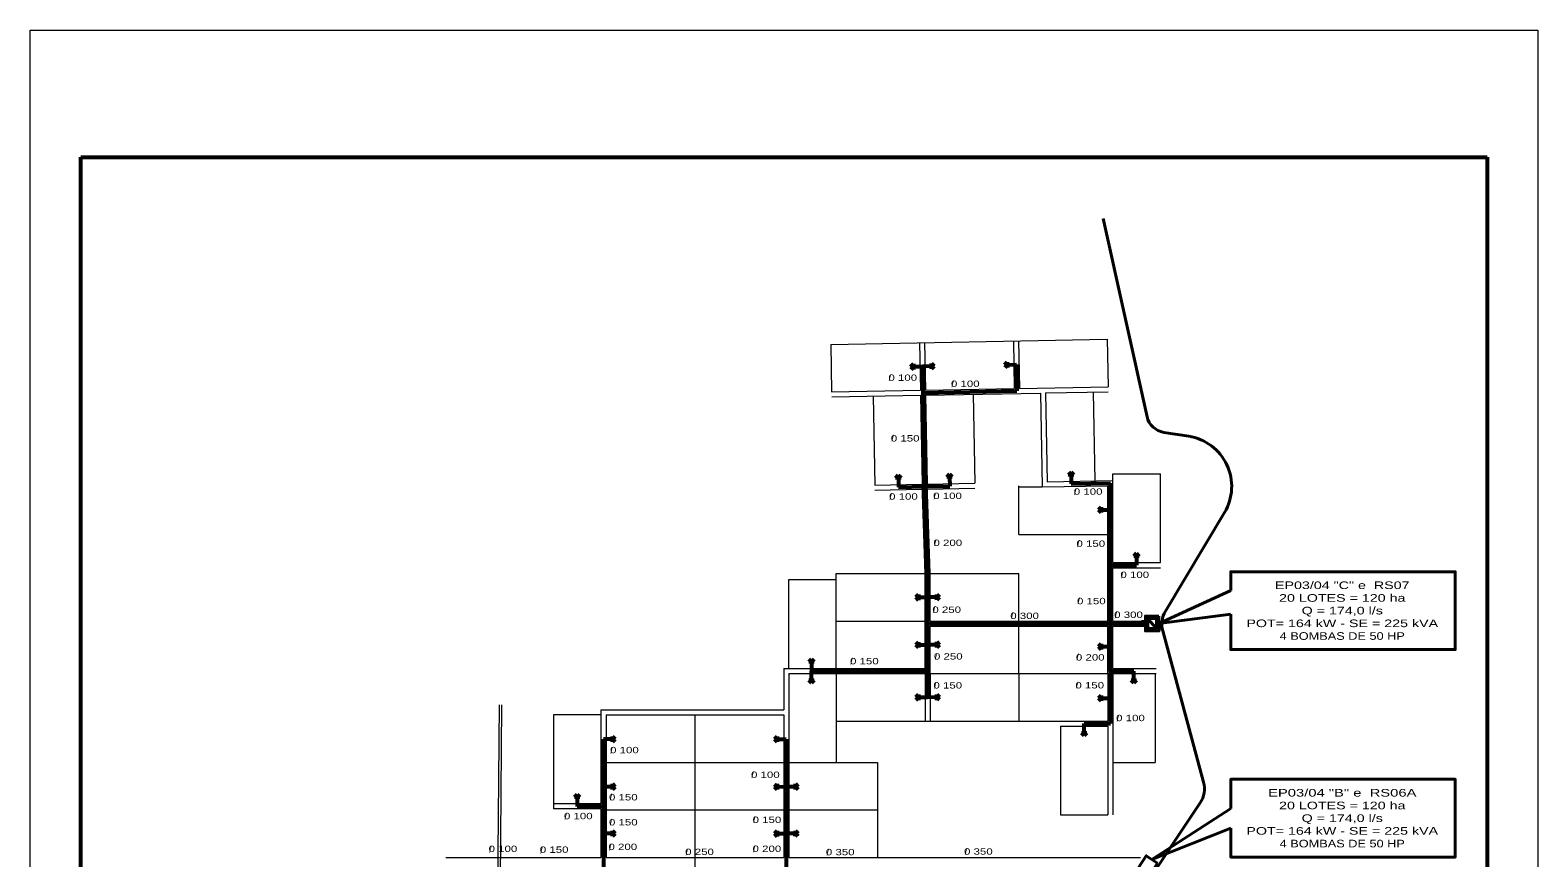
# Model space of a CAD drawing. Extents: x 312964 to 351929, y 9004151 to 9034973.
# Drawn here: x 342096 to 348036, y 9031712 to 9034973 of the extents above; entities that cross this region are included whole.
import ezdxf
from ezdxf.enums import TextEntityAlignment as Align

# ---------------------------------------------------------------- set-up
doc = ezdxf.new("R2010")
doc.units = 0
doc.header["$LTSCALE"] = 10
for name, color, linetype, lineweight in [('1', 7, 'Continuous', 13), ('2', 7, 'Continuous', 53), ('6', 7, 'Continuous', 13)]:
    doc.layers.add(name, color=color, linetype=linetype, lineweight=lineweight)

msp = doc.modelspace()

# ---------------------------------------------------------------- linework, layer by layer
at = {"layer": '1'}
for p, q in [((342096.46, 9030772.79), (342096.46, 9034972.79)), ((345250.43, 9033734.99), (345253.92, 9033548.02)), ((345600.37, 9033741.53), (345603.86, 9033554.56)), ((345620.36, 9033741.9), (345623.86, 9033554.94)), ((345970.3, 9033748.45), (345973.8, 9033561.48)), ((345990.3, 9033748.82), (345993.79, 9033561.85)), ((345253.92, 9033548.02), (345603.86, 9033554.56)), ((345623.86, 9033554.94), (345973.8, 9033561.48)), ((345993.79, 9033561.85), (346343.73, 9033568.39)), ((345254.3, 9033528.03), (345604.24, 9033534.57)), ((345417.27, 9033531.07), (345423.81, 9033181.13)), ((345604.24, 9033534.57), (345610.78, 9033184.49)), ((345624.23, 9033534.94), (346077.15, 9033543.41)), ((345624.23, 9033534.94), (345630.77, 9033185)), ((345811.2, 9033538.44), (345817.74, 9033188.5)), ((346097.15, 9033543.78), (346344.11, 9033548.4)), ((346097.15, 9033543.78), (346103.69, 9033193.84)), ((346284.12, 9033547.28), (346290.66, 9033197.34)), ((346103.69, 9033193.84), (346362.24, 9033198.67)), ((346362.24, 9033225.36), (346549.24, 9033225.36)), ((346362.24, 9032875.36), (346362.24, 9033225.36)), ((346549.24, 9032875.36), (346549.24, 9033225.36)), ((345423.81, 9033181.13), (345610.78, 9033184.63)), ((345424.18, 9033161.14), (345611.15, 9033164.63)), ((345622.24, 9032832.03), (345610.78, 9033184.49)), ((345630.77, 9033185), (345817.74, 9033188.5)), ((345642.24, 9032832.36), (345630.77, 9033185)), ((345631.15, 9033165.01), (345818.12, 9033168.5)), ((345992.24, 9032986.47), (345992.24, 9033178.3)), ((345992.24, 9033173.47), (346084.07, 9033173.47)), ((346342.24, 9032645.36), (346342.24, 9033178.3)), ((345992.24, 9032986.47), (346342.24, 9032986.47)), ((346362.24, 9032875.36), (346549.24, 9032875.36)), ((346362.24, 9032855.36), (346549.24, 9032855.36)), ((346362.24, 9032645.36), (346362.24, 9032855.36)), ((345085.24, 9032458.36), (345085.24, 9032808.36)), ((345085.24, 9032808.36), (345272.24, 9032808.36)), ((345272.24, 9032458.36), (345272.24, 9032832.36)), ((345272.24, 9032832.36), (345622.24, 9032832.36)), ((345622.24, 9032458.36), (345622.24, 9032832.03)), ((345642.24, 9032832.36), (345992.24, 9032832.36)), ((345642.24, 9032645.36), (345642.24, 9032832.36)), ((345992.24, 9032645.36), (345992.24, 9032832.36)), ((345272.24, 9032645.36), (345622.24, 9032645.36)), ((345642.24, 9032645.36), (346342.24, 9032645.36)), ((345642.24, 9032625.36), (346342.24, 9032625.36)), ((345642.24, 9032438.36), (345642.24, 9032625.36)), ((345992.24, 9032438.36), (345992.24, 9032625.36)), ((346342.24, 9032438.36), (346342.24, 9032625.36)), ((346362.24, 9032645.36), (346475.44, 9032645.36)), ((346362.24, 9032625.36), (346475.49, 9032625.36)), ((346362.24, 9032458.36), (346362.24, 9032625.36)), ((345065.24, 9032458.36), (345065.24, 9032295.36)), ((345065.24, 9032458.36), (345622.24, 9032458.36)), ((345085.24, 9032438.36), (345622.24, 9032438.36)), ((345085.24, 9032438.36), (345085.24, 9031714.36)), ((345272.24, 9032438.36), (345272.24, 9032088.36)), ((345622.24, 9032438.36), (345622.24, 9032251.36)), ((345642.24, 9032438.36), (345642.24, 9032251.36)), ((345642.24, 9032438.36), (346342.24, 9032438.36)), ((345992.24, 9032438.36), (345992.24, 9032251.36)), ((346342.24, 9032438.36), (346342.24, 9032251.36)), ((346362.24, 9032458.36), (346532.23, 9032458.36)), ((346362.24, 9032438.36), (346362.24, 9031881.36)), ((346362.24, 9032438.36), (346532.28, 9032438.36)), ((346529.24, 9032438.36), (346529.24, 9032088.36)), ((344158.24, 9032275.36), (344158.24, 9031905.36)), ((344345.24, 9032275.36), (344158.24, 9032275.36)), ((344345.24, 9032295.36), (345065.24, 9032295.36)), ((344345.24, 9032295.36), (344345.24, 9031925.36)), ((344365.24, 9032275.36), (345065.24, 9032275.36)), ((344365.24, 9032275.36), (344365.24, 9031714.36)), ((344715.24, 9032275.36), (344715.24, 9030385.36)), ((345065.24, 9032275.36), (345065.24, 9031714.36)), ((345272.24, 9032251.36), (346342.24, 9032251.36)), ((346155.24, 9032231.36), (346342.24, 9032231.36)), ((346155.24, 9032231.36), (346155.24, 9031881.36)), ((346342.24, 9032231.36), (346342.24, 9031881.36)), ((344365.24, 9032088.36), (345435.24, 9032088.36)), ((345085.24, 9032088.36), (345435.24, 9032088.36)), ((345435.24, 9032088.36), (345435.24, 9031714.36)), ((346362.24, 9032088.36), (346529.24, 9032088.36)), ((344345.24, 9031925.36), (344158.24, 9031925.36)), ((344345.24, 9031905.36), (344158.24, 9031905.36)), ((344345.24, 9031905.36), (344345.24, 9031714.36)), ((344365.24, 9031901.36), (345065.24, 9031901.36)), ((345085.24, 9031901.36), (345435.24, 9031901.36)), ((346155.24, 9031881.36), (346342.24, 9031881.36)), ((343734.24, 9031714.36), (344345.24, 9031714.36)), ((344365.24, 9031714.36), (345065.24, 9031714.36))]:
    msp.add_line(p, q, dxfattribs=at)
at = {"layer": '1', "lineweight": 53}
for p, q in [((342296.46, 9026772.79), (342296.46, 9034472.79)), ((342296.46, 9034472.79), (347836.46, 9034472.79)), ((347836.46, 9034472.79), (347836.46, 9026772.79))]:
    msp.add_line(p, q, dxfattribs=at)
at = {"layer": '1', "lineweight": 40}
for p, q in [((346496.92, 9033450.17), (346323.74, 9034231.36)), ((346661.08, 9033373.09), (346562.69, 9033388.44)), ((346569.07, 9032683.84), (346801.86, 9033072.77)), ((346490.49, 9032627.9), (346475.45, 9032642.86)), ((346490.45, 9032642.9), (346475.49, 9032627.86)), ((346500.42, 9032654.58), (346533.9, 9032616.34)), ((346719.85, 9032010.25), (346558.36, 9032606.33)), ((346471.21, 9031576.37), (346706.48, 9031928.55))]:
    msp.add_line(p, q, dxfattribs=at)
at = {"layer": '1'}
for points in [[(342096.46, 9034972.79), (348036.46, 9034972.79), (348036.46, 9030772.79)], [(345250.43, 9033734.99), (346340.24, 9033755.36), (346343.73, 9033568.39)], [(346077.15, 9033543.41), (346084.07, 9033173.47), (346342.24, 9033178.3)], [(345085.24, 9031714.36), (345435.24, 9031714.36), (346471.5, 9031714.36)]]:
    msp.add_lwpolyline(points, dxfattribs=at)
at = {"layer": '1', "lineweight": 40}
for points in [[(346543.78, 9032664.69), (346543.93, 9032606.37), (346490.54, 9032606.24), (346490.4, 9032664.56)], [(346475.45, 9032642.86), (346475.49, 9032627.86), (346490.49, 9032627.9), (346490.45, 9032642.9)], [(346533.81, 9032654.67), (346533.9, 9032616.34), (346500.52, 9032616.26), (346500.42, 9032654.58)], [(346500.42, 9032654.58), (346533.81, 9032654.67), (346533.9, 9032616.34)], [(346538.12, 9031691.25), (346506.14, 9031642.47), (346461.49, 9031671.75), (346493.47, 9031720.52)]]:
    msp.add_lwpolyline(points, close=True, dxfattribs=at)
for centre, radius, start, end in [((346575.02, 9033467.49), 80, 192.49974, 261.1331), ((346630.25, 9033175.48), 200, 329.09823, 81.13306), ((346654.88, 9032632.48), 100, 149.09824, 195.159), ((346623.33, 9031984.1), 100, 326.25468, 15.15895)]:
    msp.add_arc(centre, radius, start, end, dxfattribs=at)
at = {"layer": '2'}
for p, q in [((345565.5, 9033647.11), (345576.08, 9033658.09)), ((345565.5, 9033647.11), (345576.48, 9033636.53)), ((345576.08, 9033658.09), (345576.48, 9033636.53)), ((345576.27, 9033647.57), (345612.11, 9033648.23)), ((345647.96, 9033648.9), (345612.11, 9033648.23)), ((345612.11, 9033648.23), (345614.05, 9033544.75)), ((345648.15, 9033638.38), (345647.75, 9033659.94)), ((345658.73, 9033649.36), (345647.75, 9033659.94)), ((345658.73, 9033649.36), (345648.15, 9033638.38)), ((345935.43, 9033654.02), (345946.01, 9033665)), ((345935.43, 9033654.02), (345946.41, 9033643.45)), ((345946.01, 9033665), (345946.41, 9033643.45)), ((345946.21, 9033654.48), (345982.05, 9033655.15)), ((345982.05, 9033655.15), (345983.98, 9033551.67)), ((345614.05, 9033544.75), (345983.98, 9033551.67)), ((345614.05, 9033544.75), (345620.78, 9033184.82)), ((345516.49, 9033219.5), (345505.91, 9033208.52)), ((345527.47, 9033208.92), (345505.91, 9033208.52)), ((345516.49, 9033219.5), (345527.47, 9033208.92)), ((345516.95, 9033208.73), (345517.62, 9033172.89)), ((345718.52, 9033223.28), (345707.95, 9033212.3)), ((345729.5, 9033212.7), (345707.95, 9033212.3)), ((345718.52, 9033223.28), (345729.5, 9033212.7)), ((345718.98, 9033212.5), (345719.65, 9033176.66)), ((346197.26, 9033232.22), (346186.44, 9033221.48)), ((346208, 9033221.4), (346186.44, 9033221.48)), ((346197.26, 9033232.22), (346208, 9033221.4)), ((346197.48, 9033221.44), (346197.36, 9033185.59)), ((345517.62, 9033172.89), (345621.1, 9033174.82)), ((345616.17, 9033174.73), (345719.65, 9033176.66)), ((345632.24, 9032832.04), (345620.78, 9033184.68)), ((346197.36, 9033185.59), (346352.24, 9033188.49)), ((346352.24, 9032448.36), (346352.24, 9033188.49)), ((346305.61, 9033083.57), (346316.43, 9033094.32)), ((346305.61, 9033083.57), (346316.35, 9033072.76)), ((346316.43, 9033094.32), (346316.35, 9033072.76)), ((346316.39, 9033083.79), (346352.24, 9033083.67)), ((346455.64, 9032911.99), (346444.82, 9032901.25)), ((346466.38, 9032901.17), (346444.82, 9032901.25)), ((346455.64, 9032911.99), (346466.38, 9032901.17)), ((346455.86, 9032901.21), (346455.74, 9032865.36)), ((346352.24, 9032865.36), (346455.74, 9032865.36)), ((345585.61, 9032738.76), (345596.43, 9032749.5)), ((345585.61, 9032738.76), (345596.35, 9032727.94)), ((345596.43, 9032749.5), (345596.35, 9032727.94)), ((345596.39, 9032738.98), (345632.24, 9032738.86)), ((345668.09, 9032738.74), (345632.24, 9032738.86)), ((345668.05, 9032728.22), (345668.12, 9032749.78)), ((345678.87, 9032738.96), (345668.05, 9032728.22)), ((345678.87, 9032738.96), (345668.12, 9032749.78)), ((345632.24, 9032635.36), (346475.47, 9032635.36)), ((345585.61, 9032551.76), (345596.43, 9032562.5)), ((345585.61, 9032551.76), (345596.35, 9032540.94)), ((345596.43, 9032562.5), (345596.35, 9032540.94)), ((345596.39, 9032551.98), (345632.24, 9032551.86)), ((345668.09, 9032551.74), (345632.24, 9032551.86)), ((345668.05, 9032541.22), (345668.12, 9032562.78)), ((345678.87, 9032551.96), (345668.05, 9032541.22)), ((345678.87, 9032551.96), (345668.12, 9032562.78)), ((346305.61, 9032544.34), (346316.43, 9032555.08)), ((346305.61, 9032544.34), (346316.35, 9032533.52)), ((346316.43, 9032555.08), (346316.35, 9032533.52)), ((346316.39, 9032544.56), (346352.24, 9032544.44)), ((345174.72, 9032494.99), (345163.9, 9032484.25)), ((345185.46, 9032484.17), (345163.9, 9032484.25)), ((345174.72, 9032494.99), (345185.46, 9032484.17)), ((345174.94, 9032484.21), (345174.82, 9032448.36)), ((345174.7, 9032412.51), (345174.82, 9032448.36)), ((345632.24, 9032448.36), (345632.24, 9032344.86)), ((346352.24, 9032448.36), (346352.24, 9032241.36)), ((346352.24, 9032448.36), (346444.41, 9032448.36)), ((346444.29, 9032412.51), (346444.41, 9032448.36)), ((345164.18, 9032412.55), (345185.74, 9032412.47)), ((345174.92, 9032401.73), (345164.18, 9032412.55)), ((345174.92, 9032401.73), (345185.74, 9032412.47)), ((346433.77, 9032412.55), (346455.33, 9032412.47)), ((346444.51, 9032401.73), (346433.77, 9032412.55)), ((346444.51, 9032401.73), (346455.33, 9032412.47)), ((345585.61, 9032344.76), (345596.43, 9032355.5)), ((345585.61, 9032344.76), (345596.35, 9032333.94)), ((345596.43, 9032355.5), (345596.35, 9032333.94)), ((345596.39, 9032344.98), (345632.24, 9032344.86)), ((345668.09, 9032344.74), (345632.24, 9032344.86)), ((345668.05, 9032334.22), (345668.12, 9032355.78)), ((345678.87, 9032344.96), (345668.05, 9032334.22)), ((345678.87, 9032344.96), (345668.12, 9032355.78)), ((346305.61, 9032341.21), (346316.43, 9032351.95)), ((346305.61, 9032341.21), (346316.35, 9032330.39)), ((346316.43, 9032351.95), (346316.35, 9032330.39)), ((346316.39, 9032341.43), (346352.24, 9032341.31)), ((344391.05, 9032169.56), (344391.12, 9032191.12)), ((344401.87, 9032180.3), (344391.12, 9032191.12)), ((345028.61, 9032179.73), (345039.43, 9032190.47)), ((345039.43, 9032190.47), (345039.35, 9032168.91)), ((346238.1, 9032205.55), (346259.66, 9032205.47)), ((346248.84, 9032194.73), (346238.1, 9032205.55)), ((346248.62, 9032205.51), (346248.74, 9032241.36)), ((346248.74, 9032241.36), (346352.24, 9032241.36)), ((346248.84, 9032194.73), (346259.66, 9032205.47)), ((344391.09, 9032180.08), (344355.24, 9032180.2)), ((344401.87, 9032180.3), (344391.05, 9032169.56)), ((345028.61, 9032179.73), (345039.35, 9032168.91)), ((345039.39, 9032179.95), (345075.24, 9032179.83)), ((344251.64, 9031961.99), (344240.82, 9031951.25)), ((344262.38, 9031951.17), (344240.82, 9031951.25)), ((344251.64, 9031961.99), (344262.38, 9031951.17)), ((344251.86, 9031951.21), (344251.74, 9031915.36)), ((344391.09, 9031992.48), (344355.24, 9031992.6)), ((344391.05, 9031981.96), (344391.12, 9032003.52)), ((344401.87, 9031992.7), (344391.05, 9031981.96)), ((344401.87, 9031992.7), (344391.12, 9032003.52)), ((345029.17, 9031992.64), (345039.98, 9032003.38)), ((345029.17, 9031992.64), (345039.91, 9031981.83)), ((345039.98, 9032003.38), (345039.91, 9031981.83)), ((345039.95, 9031992.86), (345075.79, 9031992.74)), ((345111.64, 9031992.62), (345075.79, 9031992.74)), ((345111.61, 9031982.1), (345111.68, 9032003.66)), ((345122.42, 9031992.84), (345111.61, 9031982.1)), ((345122.42, 9031992.84), (345111.68, 9032003.66)), ((344355.24, 9031915.36), (344251.74, 9031915.36)), ((344391.09, 9031807.74), (344355.24, 9031807.86)), ((344391.05, 9031797.22), (344391.12, 9031818.78)), ((344401.87, 9031807.96), (344391.05, 9031797.22)), ((344401.87, 9031807.96), (344391.12, 9031818.78)), ((345028.61, 9031807.76), (345039.43, 9031818.5)), ((345028.61, 9031807.76), (345039.35, 9031796.94)), ((345039.43, 9031818.5), (345039.35, 9031796.94)), ((345039.39, 9031807.98), (345075.24, 9031807.86)), ((345111.09, 9031807.74), (345075.24, 9031807.86)), ((345111.05, 9031797.22), (345111.12, 9031818.78)), ((345121.87, 9031807.96), (345111.05, 9031797.22)), ((345121.87, 9031807.96), (345111.12, 9031818.78))]:
    msp.add_line(p, q, dxfattribs=at)
at = {"layer": '2', "lineweight": 40}
for p in [(346826.7, 9031907.46), (346826.7, 9031829.31)]:
    msp.add_line(p, (346515.8, 9031705.88), dxfattribs=at)
for points in [[(347004.19, 9032839.61), (347710.93, 9032839.61), (347710.93, 9032532.78), (346826.7, 9032532.78), (346826.7, 9032672.27)], [(346826.7, 9032765.47), (346826.7, 9032839.61), (347004.19, 9032839.61)], [(346826.7, 9032765.47), (346543.86, 9032635.53), (346826.7, 9032672.27)], [(347004.19, 9032022.03), (347710.93, 9032022.03), (347710.93, 9031715.2), (346826.7, 9031715.2), (346826.7, 9031829.31)], [(346826.7, 9031907.46), (346826.7, 9032022.03), (347004.19, 9032022.03)]]:
    msp.add_lwpolyline(points, dxfattribs=at)
at = {"layer": '2'}
for points in [[(345174.82, 9032448.36), (345632.24, 9032448.36), (345632.24, 9032832.36)], [(344355.24, 9032180.2), (344355.24, 9031704.36), (344355.24, 9031432.6)], [(345075.24, 9032179.83), (345075.24, 9031704.36), (345075.24, 9031433.86)]]:
    msp.add_lwpolyline(points, dxfattribs=at)
at = {"layer": '6'}
msp.add_line((343935.24, 9031098.44), (343945.24, 9032315.44), dxfattribs=at)
msp.add_lwpolyline([(343925.24, 9028600.36), (343934.24, 9029095.36), (343930.24, 9029625.36), (343925.24, 9030387.36), (343945.24, 9031098.36), (343955.24, 9032315.36)], dxfattribs=at)

# ---------------------------------------------------------------- texts
at = {"layer": '2'}
for p in [(345483.57, 9033590.74), (345731.05, 9033566.83), (345494.67, 9033352.9), (345486.74, 9033122.81), (345660.67, 9033125.05), (346214.41, 9033142.08), (345662.25, 9032940.69), (346226.04, 9032937.52), (346398.71, 9032814.05), (346228.15, 9032712.45), (345658.37, 9032677.71), (345965.85, 9032655.13), (346374.18, 9032656.52), (345332.95, 9032474.34), (345665.52, 9032493.36), (346223.47, 9032491.29), (345662.35, 9032379.24), (346221.36, 9032380.34), (346381.84, 9032249.32), (344387.09, 9032122.95), (344942.84, 9032026.89), (344385.02, 9031939.61), (344206.59, 9031863.54), (344385.02, 9031840.29), (344949.48, 9031850.84), (343909.66, 9031733.03), (344111.33, 9031729.66), (344381.77, 9031740.89), (344683.63, 9031722.91), (344948.92, 9031735.16), (345239.08, 9031721.78), (345783.88, 9031725.16)]:
    msp.add_text('/', height=25, dxfattribs=at).set_placement(p, align=Align.CENTER)
for s, height, width, p in [('0 100', 25, 1.35, (345534.26, 9033591.41)), ('0 100', 25, 1.35, (345780.76, 9033567.5)), ('0 150', 25, 1.35, (345543.85, 9033352.44)), ('0 100', 25, 1.35, (345536.91, 9033123.47)), ('0 100', 25, 1.35, (345710.84, 9033125.72)), ('0 100', 25, 1.35, (346264.65, 9033142.65)), ('0 200', 25, 1.35, (345711.75, 9032940.92)), ('0 150', 25, 1.35, (346275.21, 9032937.66)), ('0 100', 25, 1.35, (346448.35, 9032815.09)), ('EP03/04 "C" e  RS07', 30, 1.4, (347265.88, 9032771.27)), ('0 150', 25, 1.35, (346277.32, 9032711.54)), ('20 LOTES = 120 ha', 30, 1.4, (347265.88, 9032721.27)), ('0 250', 25, 1.35, (345707.47, 9032677.45)), ('0 300', 25, 1.35, (346014.41, 9032653.42)), ('0 300', 25, 1.35, (346423.8, 9032657.64)), ('Q = 174,0 l/s', 30, 1.4, (347265.88, 9032671.27)), ('POT= 164 kW - SE = 225 kVA', 30, 1.4, (347265.88, 9032621.27)), ('4 BOMBAS DE 50 HP', 30, 1.25, (347265.88, 9032571.27)), ('0 150', 25, 1.35, (345383.07, 9032474.75)), ('0 250', 25, 1.35, (345713.8, 9032493.6)), ('0 200', 25, 1.35, (346273.09, 9032489.65)), ('0 150', 25, 1.35, (345711.69, 9032379.48)), ('0 150', 25, 1.35, (346270.98, 9032379.76)), ('0 100', 25, 1.35, (346431.46, 9032250.85)), ('0 100', 25, 1.35, (344437.67, 9032124.6)), ('0 100', 25, 1.35, (344993.01, 9032027.39)), ('0 150', 25, 1.35, (344433.44, 9031938.63)), ('EP03/04 "B" e  RS06A', 30, 1.45, (347265.88, 9031953.69)), ('0 100', 25, 1.35, (344256.07, 9031864.67)), ('20 LOTES = 120 ha', 30, 1.4, (347265.88, 9031903.69)), ('0 150', 25, 1.35, (344433.41, 9031840.12)), ('0 150', 25, 1.35, (344999.34, 9031849.88)), ('POT= 164 kW - SE = 225 kVA', 30, 1.4, (347265.88, 9031803.69)), ('Q = 174,0 l/s', 30, 1.4, (347265.88, 9031853.69)), ('4 BOMBAS DE 50 HP', 30, 1.25, (347265.88, 9031753.69)), ('0 100', 25, 1.35, (343959.24, 9031735.54)), ('0 150', 25, 1.35, (344160.91, 9031732.17)), ('0 200', 25, 1.35, (344431.35, 9031743.4)), ('0 250', 25, 1.35, (344733.65, 9031723.79)), ('0 200', 25, 1.35, (344999.15, 9031735.8)), ('0 350', 25, 1.35, (345287.99, 9031722.66)), ('0 350', 25, 1.35, (345832.23, 9031724.94))]:
    msp.add_text(s, height=height, dxfattribs=dict(at, width=width)).set_placement(p, align=Align.CENTER)

doc.saveas('drawing.dxf')
